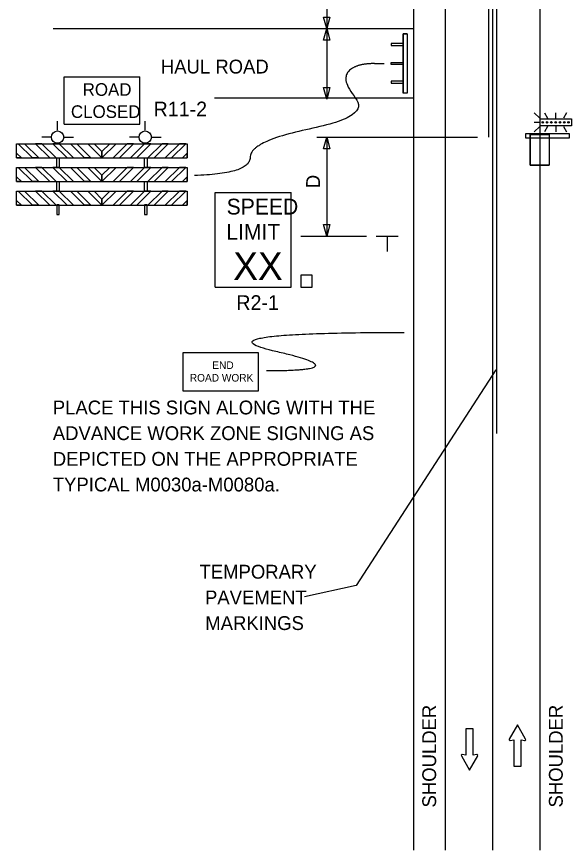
# Model space of a CAD drawing. Extents: x 16735 to 18477, y 4638 to 5631.
# Drawn here: x 16734.6 to 17015.5, y 4802 to 5224 of the extents above; entities that cross this region are included whole.
import ezdxf

# ---------------------------------------------------------------- set-up
doc = ezdxf.new("R2010")
doc.units = 0
for name, color, linetype in [('ALI_LEGAL_EX', 7, 'Continuous'), ('MT_SCRATCH_LEVEL_E', 7, 'Continuous'), ('PAVT_EDGE_EX', 7, 'Continuous'), ('TRAFFIC_SIGNS_PR', 7, 'Continuous'), ('TYPICAL_TEXT_DIMEN_PR', 7, 'Continuous')]:
    doc.layers.add(name, color=color, linetype=linetype)

msp = doc.modelspace()

# ---------------------------------------------------------------- linework, layer by layer
at = {"layer": 'ALI_LEGAL_EX'}
for p, q in [((16973.59, 5387.98), (16973.59, 5163)), ((16977.59, 5237.98), (16977.59, 5013))]:
    msp.add_line(p, q, dxfattribs=at)
at = {"layer": 'MT_SCRATCH_LEVEL_E'}
for p, q in [((16965.79, 4863.55), (16962.05, 4863.55)), ((16962.05, 4863.55), (16962.05, 4850.29)), ((16965.79, 4863.55), (16962.05, 4863.55)), ((16962.05, 4863.55), (16962.05, 4850.29)), ((16965.79, 4850.29), (16965.79, 4863.55)), ((16965.79, 4850.29), (16965.79, 4863.55)), ((16988.18, 4865.5), (16984.07, 4858.26)), ((16988.18, 4865.5), (16984.07, 4858.26)), ((16992.33, 4858.26), (16988.18, 4865.5)), ((16992.33, 4858.26), (16988.18, 4865.5)), ((16984.55, 4857.58), (16986.33, 4857.89)), ((16984.55, 4857.58), (16986.33, 4857.89)), ((16986.33, 4857.89), (16986.33, 4844.64)), ((16986.33, 4857.89), (16986.33, 4844.64)), ((16990.07, 4844.64), (16990.07, 4857.89)), ((16990.07, 4857.89), (16991.85, 4857.58)), ((16990.07, 4844.64), (16990.07, 4857.89)), ((16990.07, 4857.89), (16991.85, 4857.58)), ((16959.79, 4849.93), (16963.94, 4842.68)), ((16959.79, 4849.93), (16963.94, 4842.68)), ((16962.05, 4850.29), (16960.27, 4850.61)), ((16962.05, 4850.29), (16960.27, 4850.61)), ((16963.94, 4842.68), (16968.05, 4849.93)), ((16963.94, 4842.68), (16968.05, 4849.93)), ((16967.57, 4850.61), (16965.79, 4850.29)), ((16967.57, 4850.61), (16965.79, 4850.29)), ((16986.33, 4844.64), (16990.07, 4844.64)), ((16986.33, 4844.64), (16990.07, 4844.64))]:
    msp.add_line(p, q, dxfattribs=at)
for centre, start, end in [((16984.48, 4858.04), 150.4248, 279.9638), ((16984.48, 4858.04), 150.4248, 279.9638), ((16991.92, 4858.04), 260.0362, 29.7731), ((16991.92, 4858.04), 260.0362, 29.7731), ((16960.2, 4850.15), 80.0362, 209.7731), ((16960.2, 4850.15), 80.0362, 209.7731), ((16967.64, 4850.15), 330.4248, 99.9638), ((16967.64, 4850.15), 330.4248, 99.9638)]:
    msp.add_arc(centre, 0.463, start, end, dxfattribs=at)
at = {"layer": 'PAVT_EDGE_EX'}
for p, q in [((16935.59, 5623.96), (16935.59, 4802.04)), ((16951.59, 5623.96), (16951.59, 4802.04)), ((16975.59, 5623.96), (16975.59, 4802.04)), ((16999.59, 5623.96), (16999.59, 4802.04)), ((16753.11, 5217.98), (16935.59, 5217.98)), ((16834.76, 5183), (16935.59, 5183))]:
    msp.add_line(p, q, dxfattribs=at)
for points in [[(16975.59, 5223.96), (16975.59, 5198.96)], [(16975.59, 5123.96), (16975.59, 5098.96)], [(16975.59, 5023.96), (16975.59, 4998.96)], [(16975.59, 4923.96), (16975.59, 4898.96)], [(16975.59, 4823.96), (16975.59, 4802.04)]]:
    msp.add_lwpolyline(points, dxfattribs=at)
at = {"layer": 'TRAFFIC_SIGNS_PR'}
for p, q in [((16932.29, 5215.39), (16930.29, 5215.39)), ((16930.29, 5215.39), (16930.29, 5185.39)), ((16932.29, 5215.39), (16932.29, 5185.39)), ((16758.61, 5169.57), (16758.61, 5193.57)), ((16758.61, 5193.57), (16797.01, 5193.57)), ((16797.01, 5169.57), (16797.01, 5193.57)), ((16932.29, 5185.39), (16930.29, 5185.39)), ((16999.54, 5172.58), (16996.72, 5175.4)), ((17001.83, 5175.4), (17003.46, 5172.58)), ((17007.62, 5172.58), (17007.62, 5175.4)), ((17013.09, 5175.4), (17011.47, 5172.58)), ((16755.3, 5166.61), (16755.3, 5171.1)), ((16758.61, 5169.57), (16797.01, 5169.57)), ((16799.7, 5166.61), (16799.7, 5171.1)), ((16999.54, 5170.55), (16996.72, 5170.55)), ((17001.03, 5170.55), (17001.03, 5170.55)), ((17003.2, 5170.55), (17003.2, 5170.55)), ((17005.38, 5170.55), (17005.38, 5170.55)), ((17007.55, 5170.55), (17007.55, 5170.55)), ((17009.72, 5170.55), (17009.72, 5170.55)), ((17011.9, 5170.55), (17011.9, 5170.55)), ((17014.07, 5170.55), (17014.07, 5170.55)), ((16999.54, 5168.52), (16996.72, 5165.69)), ((17003.49, 5168.52), (17001.86, 5165.69)), ((17007.62, 5168.52), (17007.62, 5165.69)), ((17011.44, 5168.52), (17013.07, 5165.69)), ((16751.75, 5163.06), (16747.32, 5163.06)), ((16758.85, 5163.06), (16763.33, 5163.06)), ((16796.15, 5163.06), (16791.72, 5163.06)), ((16803.25, 5163.06), (16807.73, 5163.06)), ((16994.6, 5164.46), (16994.6, 5148.86)), ((17004.19, 5164.46), (17004.19, 5148.86)), ((16734.61, 5159.74), (16821.01, 5159.74)), ((16734.61, 5152.54), (16734.61, 5159.74)), ((16742.61, 5152.54), (16735.41, 5159.74)), ((16745.81, 5152.54), (16738.61, 5159.74)), ((16751.41, 5152.54), (16744.21, 5159.74)), ((16754.61, 5152.54), (16747.41, 5159.74)), ((16760.21, 5152.54), (16753.01, 5159.74)), ((16763.41, 5152.54), (16756.21, 5159.74)), ((16769.01, 5152.54), (16761.81, 5159.74)), ((16772.21, 5152.54), (16765.01, 5159.74)), ((16777.81, 5152.54), (16770.61, 5159.74)), ((16777.81, 5155.74), (16773.81, 5159.74)), ((16777.81, 5152.54), (16785.01, 5159.74)), ((16777.81, 5155.74), (16781.81, 5159.74)), ((16783.41, 5152.54), (16790.61, 5159.74)), ((16786.61, 5152.54), (16793.81, 5159.74)), ((16792.21, 5152.54), (16799.41, 5159.74)), ((16795.41, 5152.54), (16802.61, 5159.74)), ((16801.01, 5152.54), (16808.21, 5159.74)), ((16804.21, 5152.54), (16811.41, 5159.74)), ((16809.81, 5152.54), (16817.01, 5159.74)), ((16813.01, 5152.54), (16820.21, 5159.74)), ((16821.01, 5159.74), (16821.01, 5152.54)), ((16737.01, 5152.54), (16734.61, 5154.94)), ((16818.61, 5152.54), (16821.01, 5154.94)), ((16734.61, 5152.54), (16821.01, 5152.54)), ((16994.6, 5148.86), (17004.19, 5148.86)), ((16734.61, 5147.74), (16821.01, 5147.74)), ((16734.61, 5140.54), (16734.61, 5147.74)), ((16742.61, 5140.54), (16735.41, 5147.74)), ((16745.81, 5140.54), (16738.61, 5147.74)), ((16751.41, 5140.54), (16744.21, 5147.74)), ((16754.61, 5140.54), (16747.41, 5147.74)), ((16760.21, 5140.54), (16753.01, 5147.74)), ((16763.41, 5140.54), (16756.21, 5147.74)), ((16769.01, 5140.54), (16761.81, 5147.74)), ((16772.21, 5140.54), (16765.01, 5147.74)), ((16777.81, 5140.54), (16770.61, 5147.74)), ((16777.81, 5143.74), (16773.81, 5147.74)), ((16777.81, 5140.54), (16785.01, 5147.74)), ((16777.81, 5143.74), (16781.81, 5147.74)), ((16783.41, 5140.54), (16790.61, 5147.74)), ((16786.61, 5140.54), (16793.81, 5147.74)), ((16792.21, 5140.54), (16799.41, 5147.74)), ((16795.41, 5140.54), (16802.61, 5147.74)), ((16801.01, 5140.54), (16808.21, 5147.74)), ((16804.21, 5140.54), (16811.41, 5147.74)), ((16809.81, 5140.54), (16817.01, 5147.74)), ((16813.01, 5140.54), (16820.21, 5147.74)), ((16821.01, 5147.74), (16821.01, 5140.54)), ((16737.01, 5140.54), (16734.61, 5142.94)), ((16734.61, 5140.54), (16821.01, 5140.54)), ((16818.61, 5140.54), (16821.01, 5142.94)), ((16734.61, 5135.74), (16821.01, 5135.74)), ((16734.61, 5128.54), (16734.61, 5135.74)), ((16742.61, 5128.54), (16735.41, 5135.74)), ((16745.81, 5128.54), (16738.61, 5135.74)), ((16751.41, 5128.54), (16744.21, 5135.74)), ((16754.61, 5128.54), (16747.41, 5135.74)), ((16760.21, 5128.54), (16753.01, 5135.74)), ((16763.41, 5128.54), (16756.21, 5135.74)), ((16769.01, 5128.54), (16761.81, 5135.74)), ((16772.21, 5128.54), (16765.01, 5135.74)), ((16777.81, 5128.54), (16770.61, 5135.74)), ((16777.81, 5131.74), (16773.81, 5135.74)), ((16777.81, 5128.54), (16785.01, 5135.74)), ((16777.81, 5131.74), (16781.81, 5135.74)), ((16783.41, 5128.54), (16790.61, 5135.74)), ((16786.61, 5128.54), (16793.81, 5135.74)), ((16792.21, 5128.54), (16799.41, 5135.74)), ((16795.41, 5128.54), (16802.61, 5135.74)), ((16801.01, 5128.54), (16808.21, 5135.74)), ((16804.21, 5128.54), (16811.41, 5135.74)), ((16809.81, 5128.54), (16817.01, 5135.74)), ((16813.01, 5128.54), (16820.21, 5135.74)), ((16821.01, 5135.74), (16821.01, 5128.54)), ((16835.16, 5135.03), (16873.56, 5135.03)), ((16835.16, 5087.03), (16835.16, 5135.03)), ((16873.56, 5087.03), (16873.56, 5135.03)), ((16737.01, 5128.54), (16734.61, 5130.94)), ((16734.61, 5128.54), (16821.01, 5128.54)), ((16818.61, 5128.54), (16821.01, 5130.94)), ((16835.16, 5087.03), (16873.56, 5087.03))]:
    msp.add_line(p, q, dxfattribs=at)
for points in [[(16932.29, 5215.39), (16932.29, 5185.39), (16930.29, 5185.39), (16930.29, 5215.39)], [(16930.29, 5210.39), (16924.29, 5210.39), (16924.29, 5209.39), (16930.29, 5209.39)], [(16930.29, 5200.89), (16930.29, 5199.89), (16924.29, 5199.89), (16924.29, 5200.89)], [(16924.29, 5191.39), (16924.29, 5190.39), (16930.29, 5190.39), (16930.29, 5191.39)], [(16999.77, 5172.35), (17015.48, 5172.35), (17015.48, 5168.75), (16999.77, 5168.75)], [(17014.6, 5164.79), (16992.21, 5164.79), (16992.21, 5162.69), (17014.6, 5162.69)], [(16994.6, 5164.46), (17004.19, 5164.46), (17004.19, 5148.86), (16994.6, 5148.86)], [(16745.81, 5152.54), (16742.61, 5152.54), (16735.41, 5159.74), (16738.61, 5159.74)], [(16754.61, 5152.54), (16747.41, 5159.74), (16744.21, 5159.74), (16751.41, 5152.54)], [(16763.41, 5152.54), (16756.21, 5159.74), (16753.01, 5159.74), (16760.21, 5152.54)], [(16772.21, 5152.54), (16769.01, 5152.54), (16761.81, 5159.74), (16765.01, 5159.74)], [(16777.81, 5152.54), (16770.61, 5159.74), (16773.81, 5159.74), (16777.81, 5155.74)], [(16777.81, 5152.54), (16777.81, 5155.74), (16781.81, 5159.74), (16785.01, 5159.74)], [(16783.41, 5152.54), (16786.61, 5152.54), (16793.81, 5159.74), (16790.61, 5159.74)], [(16792.21, 5152.54), (16795.41, 5152.54), (16802.61, 5159.74), (16799.41, 5159.74)], [(16801.01, 5152.54), (16804.21, 5152.54), (16811.41, 5159.74), (16808.21, 5159.74)], [(16809.81, 5152.54), (16813.01, 5152.54), (16820.21, 5159.74), (16817.01, 5159.74)], [(16737.01, 5152.54), (16734.61, 5152.54), (16734.61, 5154.94)], [(16818.61, 5152.54), (16821.01, 5152.54), (16821.01, 5154.94)], [(16755.01, 5147.74), (16755.01, 5152.54), (16756.21, 5152.54), (16756.21, 5147.74)], [(16799.41, 5147.74), (16799.41, 5152.54), (16800.61, 5152.54), (16800.61, 5147.74)], [(16745.81, 5140.54), (16742.61, 5140.54), (16735.41, 5147.74), (16738.61, 5147.74)], [(16754.61, 5140.54), (16747.41, 5147.74), (16744.21, 5147.74), (16751.41, 5140.54)], [(16763.41, 5140.54), (16756.21, 5147.74), (16753.01, 5147.74), (16760.21, 5140.54)], [(16772.21, 5140.54), (16769.01, 5140.54), (16761.81, 5147.74), (16765.01, 5147.74)], [(16777.81, 5140.54), (16770.61, 5147.74), (16773.81, 5147.74), (16777.81, 5143.74)], [(16777.81, 5140.54), (16777.81, 5143.74), (16781.81, 5147.74), (16785.01, 5147.74)], [(16783.41, 5140.54), (16786.61, 5140.54), (16793.81, 5147.74), (16790.61, 5147.74)], [(16792.21, 5140.54), (16795.41, 5140.54), (16802.61, 5147.74), (16799.41, 5147.74)], [(16801.01, 5140.54), (16804.21, 5140.54), (16811.41, 5147.74), (16808.21, 5147.74)], [(16809.81, 5140.54), (16813.01, 5140.54), (16820.21, 5147.74), (16817.01, 5147.74)], [(16737.01, 5140.54), (16734.61, 5140.54), (16734.61, 5142.94)], [(16755.01, 5135.74), (16755.01, 5140.54), (16756.21, 5140.54), (16756.21, 5135.74)], [(16799.41, 5135.74), (16799.41, 5140.54), (16800.61, 5140.54), (16800.61, 5135.74)], [(16818.61, 5140.54), (16821.01, 5140.54), (16821.01, 5142.94)], [(16745.81, 5128.54), (16742.61, 5128.54), (16735.41, 5135.74), (16738.61, 5135.74)], [(16754.61, 5128.54), (16747.41, 5135.74), (16744.21, 5135.74), (16751.41, 5128.54)], [(16763.41, 5128.54), (16756.21, 5135.74), (16753.01, 5135.74), (16760.21, 5128.54)], [(16772.21, 5128.54), (16769.01, 5128.54), (16761.81, 5135.74), (16765.01, 5135.74)], [(16777.81, 5128.54), (16770.61, 5135.74), (16773.81, 5135.74), (16777.81, 5131.74)], [(16777.81, 5128.54), (16777.81, 5131.74), (16781.81, 5135.74), (16785.01, 5135.74)], [(16783.41, 5128.54), (16786.61, 5128.54), (16793.81, 5135.74), (16790.61, 5135.74)], [(16792.21, 5128.54), (16795.41, 5128.54), (16802.61, 5135.74), (16799.41, 5135.74)], [(16801.01, 5128.54), (16804.21, 5128.54), (16811.41, 5135.74), (16808.21, 5135.74)], [(16809.81, 5128.54), (16813.01, 5128.54), (16820.21, 5135.74), (16817.01, 5135.74)], [(16737.01, 5128.54), (16734.61, 5128.54), (16734.61, 5130.94)], [(16755.01, 5128.73), (16755.01, 5123.93), (16756.21, 5123.93), (16756.21, 5128.73)], [(16799.41, 5128.73), (16799.41, 5123.93), (16800.61, 5123.93), (16800.61, 5128.73)], [(16818.61, 5128.54), (16821.01, 5128.54), (16821.01, 5130.94)], [(16878.58, 5087.03), (16884.17, 5087.03), (16884.17, 5093.2), (16878.58, 5093.2)], [(16818.68, 5034.59), (16857.08, 5034.59), (16857.08, 5053.79), (16818.68, 5053.79)]]:
    msp.add_lwpolyline(points, close=True, dxfattribs=at)
for centre, radius in [((17001.03, 5170.55), 0.379), ((17003.2, 5170.55), 0.379), ((17005.38, 5170.55), 0.379), ((17007.55, 5170.55), 0.379), ((17009.72, 5170.55), 0.379), ((17011.9, 5170.55), 0.379), ((17014.05, 5170.55), 0.379), ((16755.3, 5163.06), 3.13), ((16799.7, 5163.06), 3.13)]:
    msp.add_circle(centre, radius, dxfattribs=at)
msp.add_open_spline([(16861.15, 5044.86), (16908.39, 5044.86), (16823.37, 5064.21), (16930.76, 5064.21)], degree=2, dxfattribs=at)
at = {"layer": 'TYPICAL_TEXT_DIMEN_PR'}
for p, q in [((16891.59, 5237.98), (16891.59, 5217.98)), ((16891.59, 5217.98), (16890.02, 5223.84)), ((16890.02, 5223.84), (16891.59, 5223.84)), ((16891.59, 5223.84), (16893.16, 5223.84)), ((16893.16, 5223.84), (16891.59, 5217.98)), ((16886.59, 5217.98), (16932.29, 5217.98)), ((16890.02, 5212.12), (16891.59, 5217.98)), ((16891.59, 5217.98), (16891.59, 5182.32)), ((16891.59, 5217.98), (16893.16, 5212.12)), ((16891.59, 5212.12), (16890.02, 5212.12)), ((16893.16, 5212.12), (16891.59, 5212.12)), ((16915.78, 5200.29), (16920.65, 5200.29)), ((16891.59, 5182.32), (16890.02, 5188.18)), ((16890.02, 5188.18), (16891.59, 5188.18)), ((16891.59, 5182.32), (16890.02, 5188.18)), ((16890.02, 5188.18), (16891.59, 5188.18)), ((16891.59, 5188.18), (16893.16, 5188.18)), ((16893.16, 5188.18), (16891.59, 5182.32)), ((16891.59, 5188.18), (16893.16, 5188.18)), ((16893.16, 5188.18), (16891.59, 5182.32)), ((16886.59, 5183), (16932.29, 5183)), ((16886.59, 5163), (16968.04, 5163)), ((16890.02, 5157.14), (16891.59, 5163)), ((16891.59, 5163), (16891.59, 5113)), ((16891.59, 5163), (16893.16, 5157.14)), ((16891.59, 5157.14), (16890.02, 5157.14)), ((16893.16, 5157.14), (16891.59, 5157.14)), ((16891.59, 5113), (16890.02, 5118.86)), ((16890.02, 5118.86), (16891.59, 5118.86)), ((16891.59, 5118.86), (16893.16, 5118.86)), ((16893.16, 5118.86), (16891.59, 5113)), ((16878.55, 5113), (16911.82, 5113)), ((16916.6, 5113), (16927.85, 5113)), ((16922.22, 5113), (16922.22, 5105.22)), ((16977.22, 5045.27), (16906.57, 4936.02)), ((16906.57, 4936.02), (16880.42, 4930.28))]:
    msp.add_line(p, q, dxfattribs=at)
msp.add_open_spline([(16915.78, 5200.29), (16905.77, 5200.29), (16898.96, 5191.65), (16913.8, 5173.51), (16852.64, 5160.98), (16852.97, 5144.5), (16824.61, 5143.65)], degree=2, dxfattribs=at)

# ---------------------------------------------------------------- texts
at = {"layer": 'TRAFFIC_SIGNS_PR'}
for s, height, p in [('ROAD', 6.4, (16768.04, 5183.97)), ('CLOSED', 6.4, (16762.09, 5172.77)), ('R11-2', 7.44, (16803.93, 5173.58)), ('SPEED', 8, (16840.93, 5123.89)), ('LIMIT', 8, (16840.77, 5111.09)), ('XX', 14.031, (16844.27, 5090.79)), ('R2-1', 7.44, (16845.84, 5075.59)), ('END', 3.831, (16833.68, 5045.72)), ('ROAD WORK', 3.831, (16822.29, 5039.33)), ('PLACE THIS SIGN ALONG WITH THE', 7, (16752.91, 5022.7)), ('ADVANCE WORK ZONE SIGNING AS', 7, (16752.91, 5009.7)), ('DEPICTED ON THE APPROPRIATE', 7, (16752.91, 4996.7)), ('TYPICAL M0030a-M0080a.', 7, (16752.91, 4983.7))]:
    msp.add_text(s, height=height, dxfattribs=at).set_placement(p)
at = {"layer": 'TYPICAL_TEXT_DIMEN_PR'}
for s, p in [('HAUL ROAD', (16807.64, 5195.27)), ('TEMPORARY', (16827.2, 4939.56)), ('PAVEMENT', (16829.98, 4926.56)), ('MARKINGS', (16830.12, 4913.56))]:
    msp.add_text(s, height=7, dxfattribs=at).set_placement(p)
for s, p in [('D', (16888.2, 5137.22)), ('SHOULDER', (16947.01, 4823.72)), ('SHOULDER', (17011.12, 4823.72))]:
    msp.add_text(s, height=7, rotation=90, dxfattribs=at).set_placement(p)

doc.saveas('drawing.dxf')
